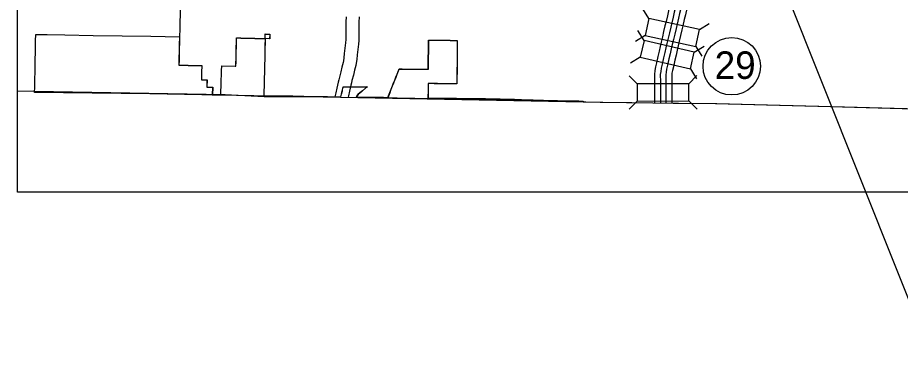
# Model space of a CAD drawing. Extents: x 670147 to 673275, y 705573 to 707613.
# Drawn here: x 670257.2 to 670561.9, y 706932.7 to 707052.8 of the extents above; entities that cross this region are included whole.
import ezdxf

# ---------------------------------------------------------------- set-up
doc = ezdxf.new("R2010")
doc.units = 0
for name, color, linetype in [('10', 7, 'Continuous'), ('19', 7, 'Continuous'), ('2', 7, 'Continuous'), ('20', 7, 'Continuous'), ('27', 7, 'Continuous'), ('6', 7, 'Continuous'), ('Default', 7, 'Continuous'), ('R_NoPlot', 7, 'Continuous')]:
    doc.layers.add(name, color=color, linetype=linetype)

msp = doc.modelspace()

# ---------------------------------------------------------------- linework, layer by layer
at = {"layer": '10'}
for points in [[(670370.56, 707053.15), (670370.5, 707051.34), (670370.48, 707049.37), (670370.47, 707047.65), (670370.46, 707045.76), (670370.43, 707045.22), (670370.35, 707044.1), (670370.16, 707042.32), (670369.96, 707040.47), (670369.8, 707038.92), (670369.66, 707037.96), (670369.52, 707037.37), (670369.13, 707035.69), (670368.74, 707034.09), (670368.25, 707032.21), (670368.03, 707031.34), (670367.85, 707030.48), (670367.36, 707028.46), (670367.01, 707026.84), (670366.65, 707025.42)], [(670375.06, 707053.09), (670375, 707051.24), (670374.98, 707049.33), (670374.97, 707047.63), (670374.95, 707045.64), (670374.92, 707044.95), (670374.83, 707043.7), (670374.64, 707041.84), (670374.43, 707040), (670374.27, 707038.37), (670374.08, 707037.1), (670373.9, 707036.34), (670373.51, 707034.65), (670373.1, 707032.98), (670372.61, 707031.1), (670372.42, 707030.32), (670372.24, 707029.49), (670371.75, 707027.46), (670371.39, 707025.81), (670371.28, 707025.38)]]:
    msp.add_lwpolyline(points, dxfattribs=at)
at = {"layer": '19'}
for points in [[(670483.25, 707061.06), (670482.92, 707059.67), (670482.37, 707057.32), (670481.84, 707055.18), (670481.47, 707053.44), (670481.02, 707051.46), (670480.63, 707049.98), (670480.2, 707048.01), (670479.75, 707046.2), (670479.3, 707044.39), (670478.99, 707042.85), (670478.62, 707041.25), (670478.19, 707039.41), (670477.72, 707037.26), (670477.35, 707035.81), (670477.12, 707034.54), (670476.99, 707033.24), (670477, 707030.67), (670477.01, 707027.75), (670477, 707025.61), (670477.04, 707023.4)], [(670485.24, 707060.51), (670484.92, 707059.19), (670484.37, 707056.84), (670483.85, 707054.72), (670483.48, 707053), (670483.02, 707050.97), (670482.64, 707049.5), (670482.21, 707047.54), (670481.75, 707045.7), (670481.31, 707043.94), (670481, 707042.41), (670480.63, 707040.79), (670480.2, 707038.95), (670479.73, 707036.78), (670479.37, 707035.37), (670479.17, 707034.25), (670479.05, 707033.14), (670479.06, 707030.68), (670479.07, 707027.75), (670479.06, 707025.61), (670479.1, 707023.38)], [(670487.07, 707060.1), (670486.75, 707058.75), (670486.2, 707056.41), (670485.68, 707054.3), (670485.31, 707052.59), (670484.85, 707050.53), (670484.46, 707049.06), (670484.03, 707047.11), (670483.57, 707045.25), (670483.14, 707043.53), (670482.83, 707042.02), (670482.46, 707040.37), (670482.03, 707038.54), (670481.56, 707036.35), (670481.2, 707034.97), (670481.02, 707033.99), (670480.93, 707033.05), (670480.94, 707030.68), (670480.94, 707027.75), (670480.93, 707025.62), (670480.97, 707023.35)], [(670489.05, 707059.5), (670488.75, 707058.27), (670488.2, 707055.93), (670487.69, 707053.83), (670487.32, 707052.15), (670486.85, 707050.04), (670486.47, 707048.57), (670486.04, 707046.64), (670485.57, 707044.75), (670485.16, 707043.07), (670484.85, 707041.58), (670484.47, 707039.9), (670484.04, 707038.08), (670483.56, 707035.88), (670483.22, 707034.53), (670483.07, 707033.7), (670482.99, 707032.95), (670483, 707030.69), (670483.01, 707027.75), (670483, 707025.63), (670483.04, 707023.33)]]:
    msp.add_lwpolyline(points, dxfattribs=at)
at = {"layer": '2'}
for points in [[(670257.19, 707027.55), (670263.02, 707027.45)], [(670263.02, 707027.45), (670328.84, 707026.29)], [(670328.84, 707026.29), (670342.31, 707025.64), (670366.65, 707025.42)], [(670371.28, 707025.38), (670382.05, 707025.28)], [(670382.05, 707025.28), (670382.05, 707025.19)], [(670382.05, 707025.19), (670418.67, 707024.59), (670458.31, 707023.6), (670476.49, 707023.4)], [(670483.51, 707023.32), (670498.06, 707023.16), (670537.81, 707022.16), (670574.89, 707021.12)]]:
    msp.add_lwpolyline(points, dxfattribs=at)
at = {"layer": '20'}
for p, q in [((670475.13, 707052.5), (670473, 707055.83)), ((670492.54, 707048.67), (670495.87, 707050.8)), ((670473.42, 707044.96), (670471.34, 707048.33)), ((670473.86, 707046.69), (670470.52, 707044.56)), ((670490.77, 707040.89), (670494.14, 707042.98)), ((670491.26, 707042.86), (670493.39, 707039.53)), ((670472.07, 707039.18), (670468.7, 707037.09)), ((670489.42, 707035.11), (670491.5, 707031.74)), ((670471.08, 707029.94), (670468.28, 707032.73)), ((670488.9, 707029.98), (670491.7, 707032.79)), ((670471.1, 707024), (670468.31, 707021.19)), ((670488.92, 707024.04), (670491.73, 707021.25))]:
    msp.add_line(p, q, dxfattribs=at)
for points in [[(670492.54, 707048.67), (670475.13, 707052.5), (670473.86, 707046.69), (670491.26, 707042.86)], [(670472.07, 707039.18), (670489.42, 707035.11), (670490.77, 707040.89), (670473.42, 707044.96)], [(670488.9, 707029.98), (670471.08, 707029.94), (670471.1, 707024), (670488.92, 707024.04)]]:
    msp.add_lwpolyline(points, close=True, dxfattribs=at)
at = {"layer": '27'}
msp.add_circle((670503.7, 707036.03), 9.9, dxfattribs=at)
at = {"layer": '6'}
for points in [[(670313.28, 707056.2), (670313.14, 707048.97), (670313.08, 707046.19), (670313.02, 707043.4), (670313, 707042.85), (670312.99, 707042.36), (670312.97, 707041.33), (670312.91, 707038.69), (670312.9, 707038.32), (670312.9, 707038.16), (670312.86, 707036.39), (670316.05, 707036.34), (670320.75, 707036.27), (670320.69, 707033.83), (670320.67, 707032.86), (670320.64, 707031.32), (670321.11, 707031.31), (670322.56, 707031.29), (670322.5, 707028.8), (670324.54, 707028.78), (670324.42, 707026.19), (670327.38, 707026.14), (670327.39, 707026.69), (670327.48, 707029.82), (670327.62, 707034.43), (670327.66, 707036.17), (670332.27, 707036.1), (670332.55, 707036.1), (670332.56, 707036.43), (670332.58, 707037.16), (670332.61, 707038.49), (670332.63, 707039.24), (670332.64, 707040), (670332.66, 707040.76), (670332.66, 707040.9), (670332.68, 707041.52), (670332.7, 707042.28), (670332.72, 707043.04), (670332.73, 707043.79), (670332.77, 707045.47), (670332.78, 707045.8), (670334.22, 707045.77), (670335.37, 707045.75), (670335.48, 707045.75), (670336.15, 707045.73), (670337.42, 707045.71), (670337.93, 707045.7), (670338.09, 707045.69), (670339.11, 707045.67), (670339.85, 707045.66), (670340.13, 707045.65), (670341.48, 707045.63), (670342.65, 707045.58)], [(670338.06, 707045.71), (670339.07, 707045.69), (670339.82, 707045.67), (670340.1, 707045.67), (670341.45, 707045.64), (670342.62, 707045.62), (670342.62, 707045.62), (670342.65, 707047.17), (670344.21, 707047.13), (670344.18, 707045.52), (670342.61, 707045.57), (670342.6, 707045.1), (670342.57, 707043.58), (670342.55, 707042.74), (670342.53, 707041.9), (670342.51, 707041.06), (670342.5, 707040.67), (670342.48, 707039.61), (670342.47, 707039.11), (670342.4, 707035.97), (670342.38, 707035.22), (670342.16, 707025.93), (670352.22, 707025.77), (670359.83, 707025.64), (670361.01, 707025.63), (670362.11, 707025.62), (670362.27, 707025.62), (670364.07, 707025.59), (670368.76, 707025.52), (670368.76, 707025.52), (670368.98, 707026.44), (670369.27, 707027.58), (670369.32, 707027.79), (670369.47, 707028.43), (670369.6, 707028.98), (670372.15, 707028.96), (670374.58, 707028.96), (670377.46, 707028.96), (670377.89, 707028.96), (670377.24, 707028.42), (670376.19, 707027.57), (670375.93, 707027.35), (670374.66, 707026.32), (670374.2, 707025.69), (670374.02, 707025.46), (670378.66, 707025.38), (670381.86, 707025.33), (670383.43, 707025.31), (670385.02, 707025.29), (670385.71, 707027.02), (670386.15, 707028.14), (670386.59, 707029.24), (670386.99, 707030.26), (670387.39, 707031.26), (670387.8, 707032.28), (670388.2, 707033.29), (670388.91, 707035.09), (670389.12, 707035.09), (670389.88, 707035.09), (670392.19, 707035.07), (670393.54, 707035.07), (670394.89, 707035.06), (670396.24, 707035.05), (670397.59, 707035.04), (670398.96, 707035.03), (670399.05, 707045.06), (670401.59, 707045.04), (670404.01, 707045.02), (670406.48, 707045), (670408.94, 707044.98), (670408.92, 707042.93), (670408.91, 707041.77), (670408.9, 707040.86), (670408.88, 707039.19), (670408.87, 707037.42), (670408.83, 707034.22), (670408.8, 707032), (670408.77, 707029.93), (670408.54, 707029.94), (670407.04, 707029.95), (670405.76, 707029.97), (670404.48, 707029.99), (670403.24, 707030), (670402.08, 707030.02), (670400.95, 707030.03), (670399.9, 707030.04), (670398.89, 707030.06), (670398.85, 707027.85), (670398.82, 707025.13)], [(670263.04, 707027.01), (670263.04, 707027.02), (670263.05, 707027.19), (670263.07, 707028.57), (670263.25, 707037.11), (670263.36, 707042.02), (670263.41, 707044.79), (670263.46, 707047), (670267.37, 707046.94), (670273.43, 707046.85), (670283.31, 707046.7), (670293.23, 707046.55), (670303.16, 707046.4), (670313.05, 707046.21)], [(670313.05, 707046.21), (670312.99, 707043.41), (670312.97, 707042.86), (670312.96, 707042.38), (670312.94, 707041.34), (670312.88, 707038.7), (670312.87, 707038.34), (670312.87, 707038.18), (670312.83, 707036.4), (670316.02, 707036.35), (670320.72, 707036.28), (670320.66, 707033.84), (670320.64, 707032.88), (670320.61, 707031.33), (670321.08, 707031.33), (670322.53, 707031.3), (670322.47, 707028.81), (670324.5, 707028.79), (670324.39, 707026.21), (670327.34, 707026.16), (670327.34, 707026.16), (670327.34, 707026.16), (670327.36, 707026.69), (670327.36, 707026.72), (670327.45, 707029.84), (670327.58, 707034.44), (670327.63, 707036.18), (670332.52, 707036.11), (670332.53, 707036.44), (670332.54, 707037.17), (670332.58, 707038.5), (670332.59, 707039.26), (670332.61, 707040.02), (670332.63, 707040.78), (670332.63, 707040.91), (670332.65, 707041.53), (670332.67, 707042.29), (670332.68, 707043.05), (670332.7, 707043.81), (670332.74, 707045.49), (670332.75, 707045.81), (670334.19, 707045.79), (670335.34, 707045.76), (670335.45, 707045.76), (670336.11, 707045.75), (670337.39, 707045.72), (670337.9, 707045.71), (670338.06, 707045.71)], [(670342.65, 707045.58), (670342.68, 707047.16), (670344.24, 707047.12), (670344.21, 707045.51), (670342.65, 707045.58), (670342.64, 707045.09), (670342.6, 707043.57), (670342.58, 707042.73), (670342.56, 707041.88), (670342.54, 707041.04), (670342.53, 707040.66), (670342.51, 707039.59), (670342.5, 707039.09), (670342.43, 707035.95), (670342.41, 707035.21), (670342.19, 707025.91), (670352.25, 707025.75), (670359.86, 707025.63), (670361.04, 707025.62), (670362.14, 707025.61), (670362.3, 707025.6), (670364.1, 707025.57), (670368.79, 707025.5), (670369.02, 707026.42), (670369.3, 707027.57), (670369.35, 707027.78), (670369.5, 707028.41), (670369.63, 707028.96), (670372.18, 707028.95), (670374.61, 707028.94), (670377.49, 707028.94), (670377.93, 707028.95), (670377.27, 707028.41), (670376.23, 707027.56), (670375.96, 707027.34), (670374.69, 707026.3), (670374.23, 707025.68)], [(670374.23, 707025.68), (670374.05, 707025.44), (670378.69, 707025.36), (670379.43, 707025.35), (670381.89, 707025.31), (670382.06, 707025.31), (670383.47, 707025.29), (670385.05, 707025.27), (670385.74, 707027.01), (670386.18, 707028.12), (670386.62, 707029.22), (670387.03, 707030.25), (670387.42, 707031.24), (670387.83, 707032.27), (670388.23, 707033.28), (670388.94, 707035.08), (670389.15, 707035.08), (670389.91, 707035.07), (670392.22, 707035.06), (670393.57, 707035.05), (670394.92, 707035.04), (670396.27, 707035.03), (670397.62, 707035.03), (670398.99, 707035.02), (670399.08, 707045.04), (670401.62, 707045.02), (670404.04, 707045), (670406.51, 707044.98), (670408.97, 707044.96), (670408.95, 707042.91), (670408.94, 707041.75), (670408.93, 707040.84), (670408.91, 707039.17), (670408.9, 707037.4), (670408.86, 707034.2), (670408.83, 707031.98), (670408.8, 707029.92), (670408.58, 707029.92), (670407.07, 707029.94), (670405.79, 707029.95), (670404.51, 707029.97), (670403.27, 707029.99), (670402.11, 707030), (670400.98, 707030.01), (670399.93, 707030.03), (670398.92, 707030.04), (670398.89, 707027.83), (670398.85, 707025.12), (670408.74, 707025), (670418.71, 707024.89), (670423.72, 707024.77), (670428.66, 707024.64), (670431.13, 707024.57), (670435.18, 707024.44), (670438.56, 707024.34), (670438.71, 707024.33), (670448.49, 707024.12), (670450.91, 707024.04), (670452.44, 707024), (670452.44, 707023.85), (670452.44, 707023.84), (670452.44, 707023.75), (670459.17, 707023.59), (670469.24, 707023.48), (670476.42, 707023.4), (670485.28, 707023.3), (670498.5, 707023.15), (670516.08, 707022.71), (670547.03, 707021.9), (670572.67, 707021.18)], [(670452.44, 707023.66), (670302.83, 707026.45), (670263.04, 707027.01)], [(670398.82, 707025.13), (670408.71, 707025.02), (670408.71, 707025.02), (670418.68, 707024.91), (670423.69, 707024.78), (670428.63, 707024.66), (670431.1, 707024.58), (670435.15, 707024.46), (670438.53, 707024.35), (670438.68, 707024.35), (670448.46, 707024.13), (670452.44, 707024), (670452.44, 707023.84), (670452.44, 707023.66)]]:
    msp.add_lwpolyline(points, dxfattribs=at)
at = {"layer": 'Default'}
msp.add_lwpolyline([(670496.38, 707126.84), (670573.69, 706933.06), (670844.37, 706932.74)], dxfattribs=at)
at = {"layer": 'R_NoPlot'}
msp.add_lwpolyline([(670257.19, 707521.73), (670842.89, 707521.73), (670842.89, 706992.57), (670257.19, 706992.57)], close=True, dxfattribs=at)

# ---------------------------------------------------------------- texts
at = {"layer": '27'}
msp.add_text('29', height=9.504, dxfattribs=at).set_placement((670497.82, 707031.66))

doc.saveas('drawing.dxf')
